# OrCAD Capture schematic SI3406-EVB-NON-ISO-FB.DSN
size B; title: Si3402 Eval Board - Isolated; rev: 2.2; note: SI3406-EVB-NON-ISO-FB
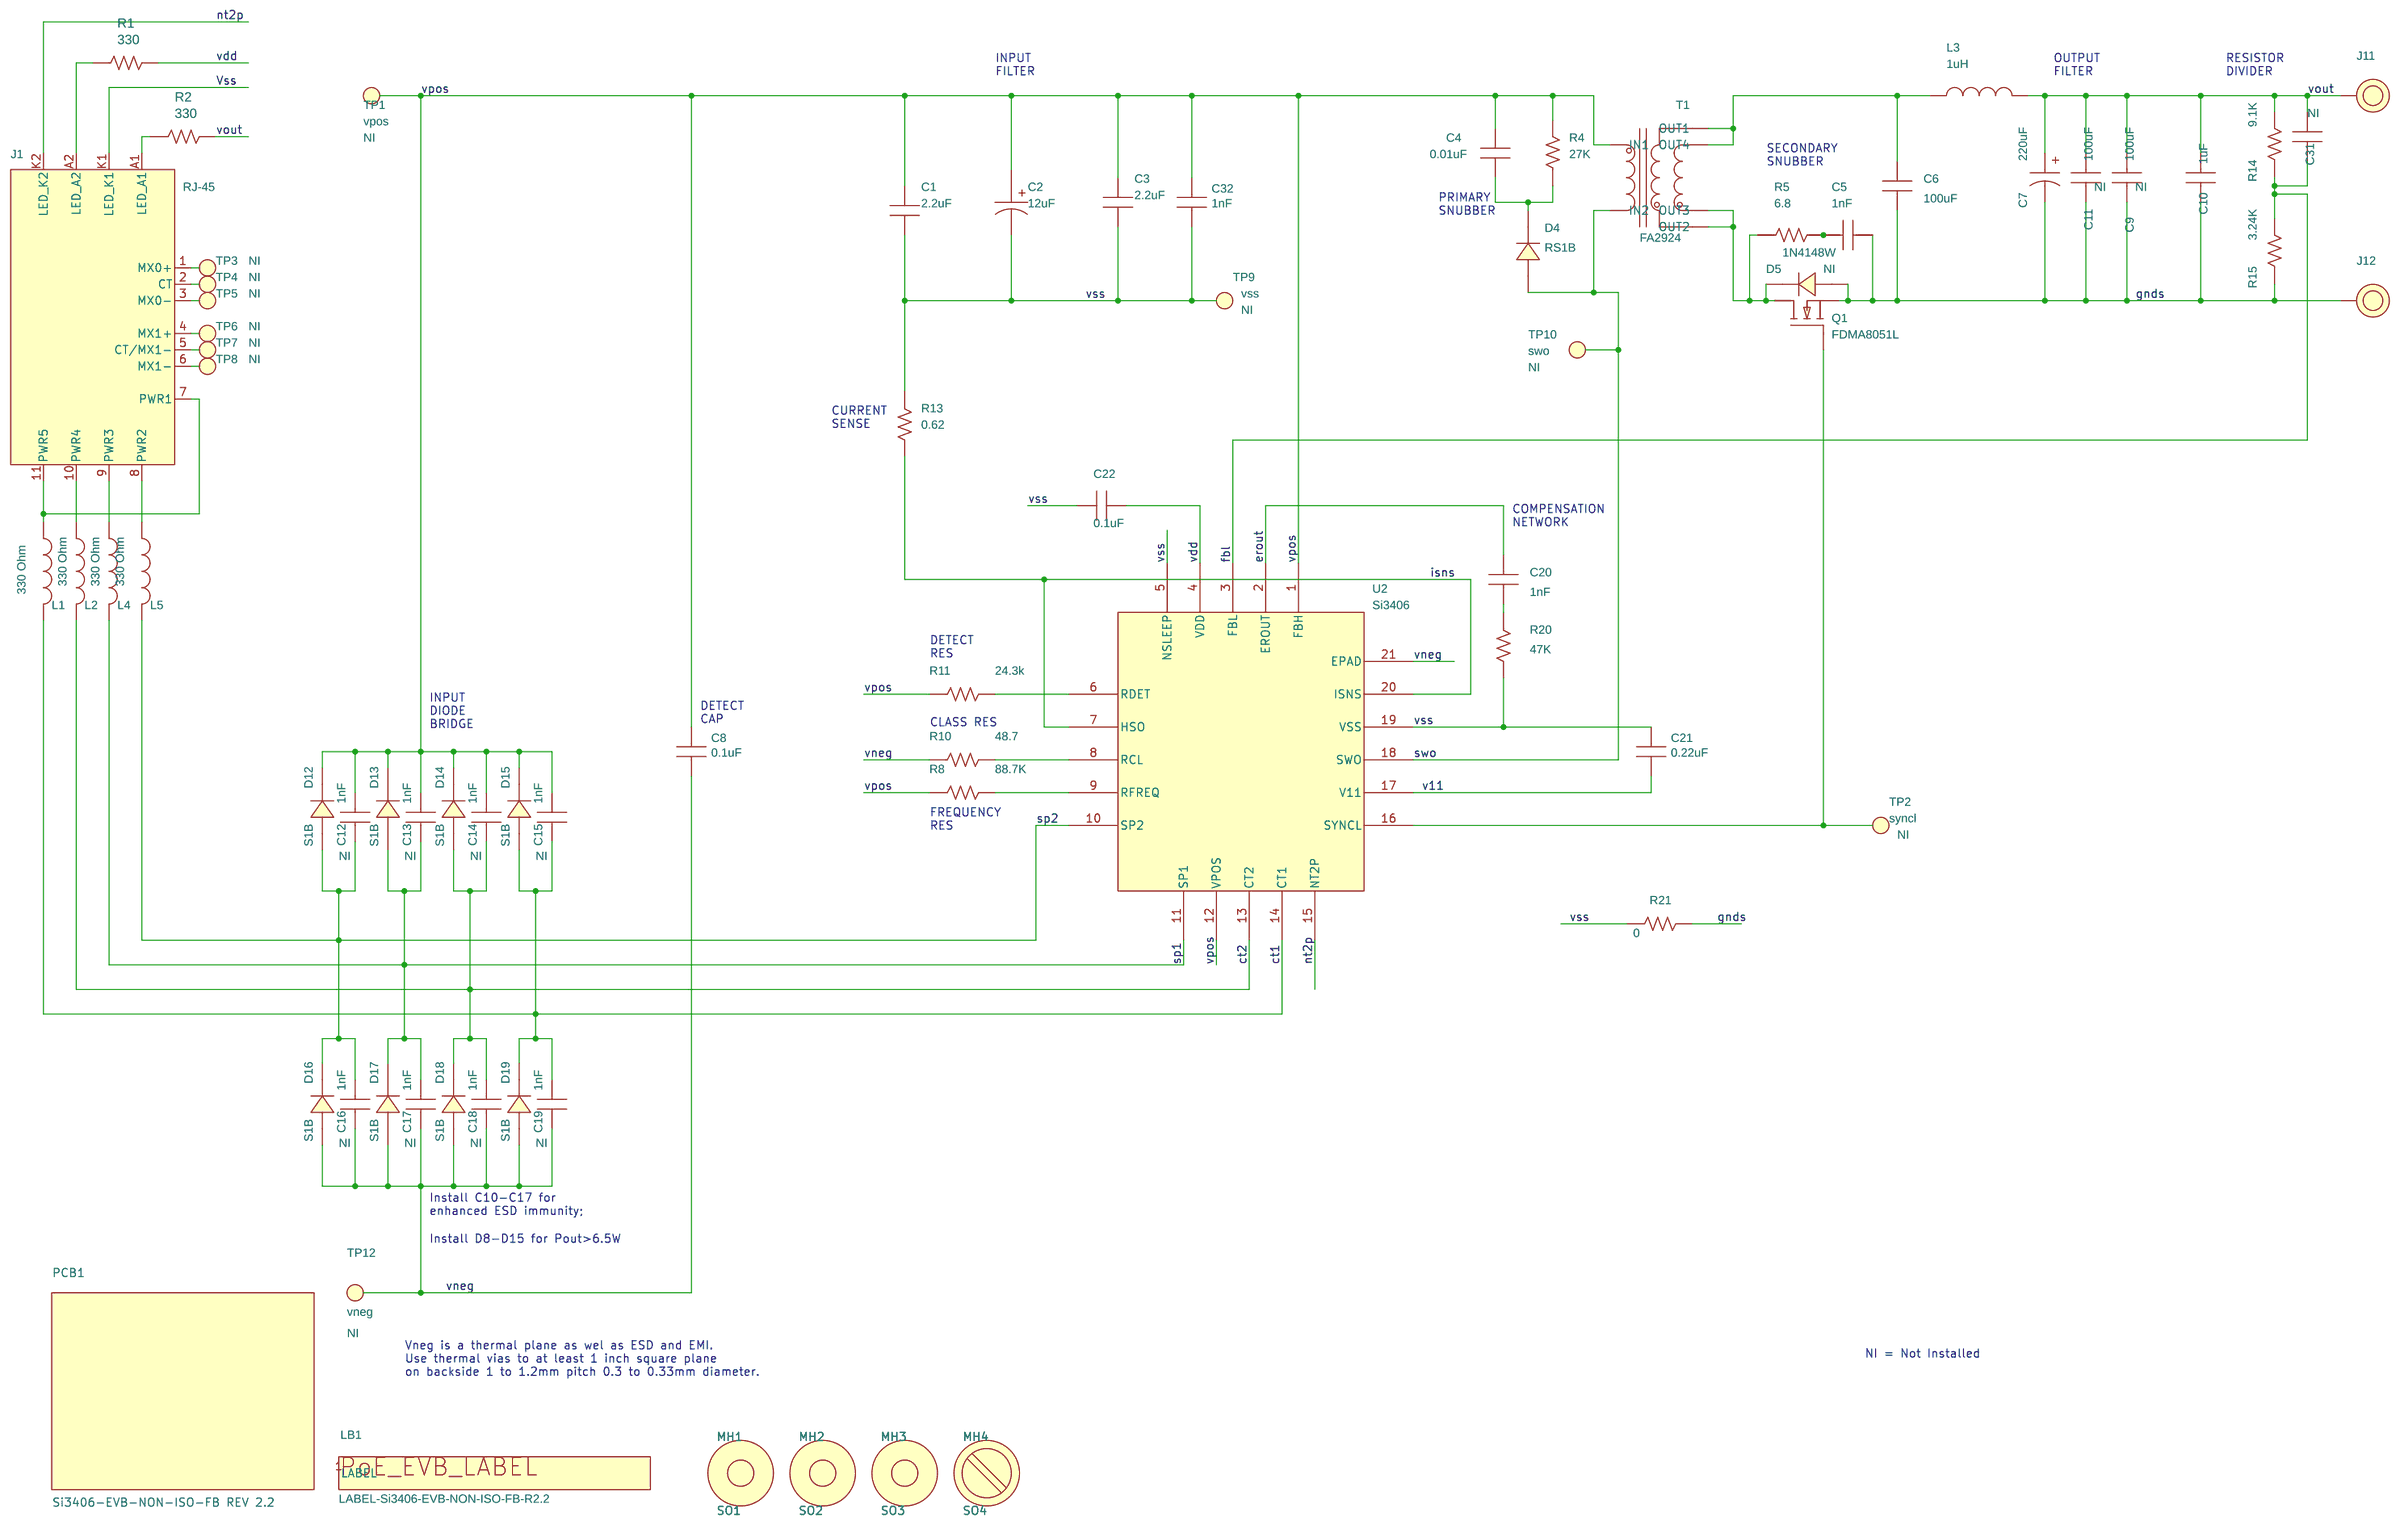
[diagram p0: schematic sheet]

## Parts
C1  2.2uF  [C1210]
C2  12uF  [C2.5X6.3MM-RAD]
C3  2.2uF  [C1210]
C4  0.01uF  [C0805]
C5  1nF  [C0805]
C6  100uF  [C1210]
C7  220uF  [C2X5MM-RAD]
C8  0.1uF  [C0805]
C9  100uF  [C1210]
C10  1uF  [C0603]
C11  100uF  [C1210]
C12  1nF  [C0603]
C13  1nF  [C0603]
C14  1nF  [C0603]
C15  1nF  [C0603]
C16  1nF  [C0603]
C17  1nF  [C0603]
C18  1nF  [C0603]
C19  1nF  [C0603]
C20  1nF  [C0805]
C21  0.22uF  [C0805]
C22  0.1uF  [C0805]
C31  330pF  [C0805]
C32  1nF  [C0603]
D4  RS1B  [DO-214AC]
D5  1N4148W  [SOD-123]
D12  S1B  [DO-214AC]
D13  S1B  [DO-214AC]
D14  S1B  [DO-214AC]
D15  S1B  [DO-214AC]
D16  S1B  [DO-214AC]
D17  S1B  [DO-214AC]
D18  S1B  [DO-214AC]
D19  S1B  [DO-214AC]
J1  RJ-45  [RJ45-SI-52004]
J11  BND_POST  [BANANA-JACK]
J12  BND_POST  [BANANA-JACK]
L1  330 Ohm  [L0805]
L2  330 Ohm  [L0805]
L3  1uH  [IND-6.6X4.45MM]
L4  330 Ohm  [L0805]
L5  330 Ohm  [L0805]
LB1  LABEL-Si3406-EVB-NON-ISO-FB-R2.2  [PTL-14-477]
MH1  4-40  [MH-125NP]
MH2  4-40  [MH-125NP]
MH3  4-40  [MH-125NP]
MH4  4-40  [MH-125NP]
PCB1  Si3406-EVB-NON-ISO-FB REV 2.2  [N/A]
Q1  FDMA8051L  [DFN6N2X2P0.65E1.0X1.05]
R1  330  [R0805]
R2  330  [R0805]
R4  27K  [R0805]
R5  6.8  [R0805]
R8  88.7K  [R0805]
R10  48.7  [R0805]
R11  24.3k  [R0805]
R13  0.62  [R0805]
R14  9.1K  [R0805]
R15  3.24K  [R0805]
R20  47K  [R0805]
R21  0  [R0805]
SO1  STANDOFF
SO2  STANDOFF
SO3  STANDOFF
SO4  STANDOFF
T1  FA2924  [XFMR-FA2924]
TP1  BLUE  [TESTPOINT]
TP2  BLUE  [TESTPOINT]
TP3  BLUE  [TESTPOINT]
TP4  BLUE  [TESTPOINT]
TP5  BLUE  [TESTPOINT]
TP6  BLUE  [TESTPOINT]
TP7  BLUE  [TESTPOINT]
TP8  BLUE  [TESTPOINT]
TP9  BLUE  [TESTPOINT]
TP10  BLUE  [TESTPOINT]
TP12  BLUE  [TESTPOINT]
U2  Si3406  [QFN20N5X5P0.8]

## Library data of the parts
C1 C3 = CAP_NP: CAP, 2.2uF, 100V, ±10%, X7R, 1210; Manufacturer: Samsung; ManufacturerPN: CL32B225KCJSNNE; SiLabsPN: CL32B225KCJSNNE; Tolerance: ±10%; Type: X7R; Voltage: 100V; Datasheet: MLCC.pdf
C2 = CAP_POL: CAP, 12uF, 100V, ±20%, AL, 6.3X11.2MM; Manufacturer: Panasonic; ManufacturerPN: EEUFC2A120; Part_Type: CAP/POL; SiLabsPN: EEUFC2A120; Tolerance: ±20%; Type: Alum_Elec; Voltage: 100V; Datasheet: ABA0000CE22.pdf
C4 = CAP_NP: CAP, 0.01uF, 100V, ±10%, X7R, 0805; Manufacturer: Venkel; ManufacturerPN: C0805X7R101-103K; SiLabsPN: C0805X7R101-103K; Tolerance: ±10%; Type: X7R; Voltage: 100V; Datasheet: PID_C.pdf
C5 C20 = CAP_NP: CAP, 1nF, 50V, ±1%, C0G, 0805; Manufacturer: Venkel; ManufacturerPN: C0805C0G500-102F; SiLabsPN: C0805C0G500-102F; Tolerance: ±1%; Type: C0G; Voltage: 50V; Datasheet: PID_C.pdf
C6 = CAP_NP: CAP, 100uF, 6.3V, ±10%, X5R, 1210; Manufacturer: Venkel; ManufacturerPN: C1210X5R6R3-107K; SiLabsPN: C1210X5R6R3-107K; Tolerance: ±10%; Type: X5R; Voltage: 6.3V; Datasheet: PID_C.pdf
C7 = CAP_POL_ALT: CAP, 220uF, 6.3V, ±20%, AL, RAD; FPLIST: C2X5MM-RAD,C2.0X5MM-RAD; Manufacturer: Panasonic; ManufacturerPN: ECA0JM221; SiLabsPN: ECA0JM221; Tolerance: ±20%; Type: Alum_Elec; Voltage: 6.3V; Datasheet: ABA0000CE12.pdf
C8 C22 = CAP_NP: CAP, 0.1uF, 100V, ±10%, X7R, 0805; Manufacturer: Venkel; ManufacturerPN: C0805X7R101-104K; SiLabsPN: C0805X7R101-104K; Tolerance: ±10%; Type: X7R; Voltage: 100V; Datasheet: PID_C.pdf
C9 C11 = CAP_NP: CAP, 100uF, 6.3V, ±10%, X5R, 1210; Installed Component: NI; Manufacturer: Venkel; ManufacturerPN: C1210X5R6R3-107K; SiLabsPN: C1210X5R6R3-107K; Tolerance: ±10%; Type: X5R; Voltage: 6.3V; Datasheet: PID_C.pdf
C10 = CAP_NP: CAP, 1uF, 6.3V, ±10%, X5R, 0603; Manufacturer: Venkel; ManufacturerPN: C0603X5R6R3-105K; SiLabsPN: C0603X5R6R3-105K; Tolerance: ±10%; Type: X5R; Voltage: 6.3V; Datasheet: PID_C.pdf
C12-C19 = CAP_NP: CAP, 1nF, 100V, ±10%, X7R, 0603; Installed Component: NI; Manufacturer: Venkel; ManufacturerPN: C0603X7R101-102K; SiLabsPN: C0603X7R101-102K; Tolerance: ±10%; Type: X7R; Voltage: 100V; Datasheet: PID_C.pdf
C21 = CAP_NP: CAP, 0.22uF, 10V, ±10%, X7R, 0805; Manufacturer: Venkel; ManufacturerPN: C0805X7R100-224K; SiLabsPN: C0805X7R100-224K; Tolerance: ±10%; Type: X7R; Voltage: 10V; Datasheet: PID_C.pdf
C31 = CAP_NP: CAP, 330pF, 100V, ±20%, X7R, 0805; Installed Component: NI; Manufacturer: Venkel; ManufacturerPN: C0805X7R101-331M; SiLabsPN: C0805X7R101-331M; Tolerance: ±20%; Type: X7R; Voltage: 100V; Datasheet: PID_C.pdf
C32 = CAP_NP: CAP, 1nF, 100V, ±10%, X7R, 0603; Manufacturer: Venkel; ManufacturerPN: C0603X7R101-102K; SiLabsPN: C0603X7R101-102K; Tolerance: ±10%; Type: X7R; Voltage: 100V; Datasheet: PID_C.pdf
D4 = DIODE: DIO, SINGLE, 100V, 1.0A, SMA; Manufacturer: Fairchild; Rating: 1.0A; Type: Single; Voltage: 100V; Datasheet: RS1A.pdf
D5 = DIODE: DIO, SINGLE, 100V, 300mA, SOD123; Installed Component: NI; Manufacturer: Diodes Inc.; ManufacturerPN: 1N4148W-7-F; Rating: 300mA; SiLabsPN: 1N4148W-7-F; Type: Single; Voltage: 100V; Datasheet: ds30086.pdf
D12-D19 = DIODE: DIO, SINGLE, 100V, 1.0A, SMA; Manufacturer: Fairchild; Rating: 1.0A; Type: Single; Voltage: 100V; Datasheet: S1A.pdf
J1 = MAGJACK_3: CONN, RJ-45, MAGJACK, 1 Port PoE; Manufacturer: Bel; ManufacturerPN: SI-52003-F; SiLabsPN: SI-52003-F; Type: Receptacle; Datasheet: SI-52003-F.pdf
J11 = BINDING-POST: CONN, BANANA JACK, Threaded uninsulated; Manufacturer: ABBATRON HH SMITH; ManufacturerPN: 101; Rating: 15A; SiLabsPN: 101; Silk: +; Type: BANANA; Datasheet: SD-101.pdf
J12 = BINDING-POST: CONN, BANANA JACK, Threaded uninsulated; Manufacturer: ABBATRON HH SMITH; ManufacturerPN: 101; Rating: 15A; SiLabsPN: 101; Type: BANANA; Datasheet: SD-101.pdf
L1 L2 L4 L5 = Ferrite_Bead: FERRITE BEAD, 330 Ohm @100MHZ, 0805; Manufacturer: MuRata; ManufacturerPN: BLM21PG331SN1; Part_Type: IND/FB; Rating: 1500mA; SiLabsPN: BLM21PG331SN1; Type: SMT; Datasheet: Murata BLM Ferrites.pdf
L3 = INDUCTOR: INDUCTOR, POWER, 1uH; Manufacturer: Coilcraft; ManufacturerPN: DO1608C-102ML_; Rating: 2.9A; SiLabsPN: DO1608C-102ML_; Tolerance: ±20%; Type: Shielded; Datasheet: do1608c.pdf
LB1 = PoE_EVB_Label: LABEL, PDB, POLYIMIDE, WHITE, 1.00 in. X 0.187 in., FONT 2; Manufacturer: Skyworks; Type: POLYIMIDE, WHITE; Datasheet: Brady TLS2200 Label PTL-14-477.pdf
MH1-MH4 = SCREW-Small: HDW, SCREW, 4-40 x 1/4 in. Pan Head, Slotted, Nylon; Manufacturer: Richco Plastic Co; ManufacturerPN: NSS-4-4-01; SiLabsPN: NSS-4-4-01; Type: SCREW; Datasheet: RichcoPlasticCo_Screws.pdf
PCB1 = PCB: PCB, BARE BOARD, Si3406-EVB-NON-ISO-FB-REV 2.2; Manufacturer: Skyworks; Type: BARE PCB
Q1 = NFET_DDGSDDD: TRANSISTOR, MOSFET, N-CHNL, 40V, 10A, 2.4W Switching Logic Level, SMT; Manufacturer: Fairchild; Rating: 10A; Type: N-CHNL; Voltage: 40V; Datasheet: FDMA8051L.pdf
R1 R2 = RES_V: RES, 330 Ohm, 1/10W, ±1%, ThickFilm, 0805; Manufacturer: Venkel; ManufacturerPN: CR0805-10W-3300F; Part_Type: RES/SMT; Rating: 1/10W; SiLabsPN: CR0805-10W-3300F; Tolerance: ±1%; Type: ThickFilm; Datasheet: PID_CR.pdf
R4 = RES: RES, 27K, 1/10W, ±1%, ThickFilm, 0805; Manufacturer: Venkel; ManufacturerPN: CR0805-10W-2702F; Rating: 1/10W; SiLabsPN: CR0805-10W-2702F; Tolerance: ±1%; Type: ThickFilm; Datasheet: PID_CR.pdf
R5 = RES: RES, 6.8 Ohm, 1/8W, ±1%, ThickFilm, 0805; Manufacturer: Yageo; ManufacturerPN: RC0805FR-076R8L; Rating: 1/8W; SiLabsPN: CR0805-8W-6R80F; Tolerance: ±1%; Type: ThickFilm; Datasheet: PID_CR.pdf
R8 = RES: RES, 88.7K, 1/8W, ±1%, ThickFilm, 0805; Manufacturer: Vishay; ManufacturerPN: CRCW080588K7FKEA; Rating: 1/8W; SiLabsPN: CR0805-8W-8872F; Tolerance: ±1%; Type: ThickFilm; Datasheet: dcrcwe3-109170.pdf
R10 = RES: RES, 48.7 Ohm, 1/8W, ±1%, ThickFilm, 0805; Manufacturer: vishay; ManufacturerPN: CRCW080548R7FKTA; Rating: 1/8W; SiLabsPN: CR0805-8W-48R7F; Tolerance: ±1%; Type: ThickFilm; Datasheet: dcrcwe3-109170.pdf
R11 = RES: RES, 24.3k, 1/8W, ±1%, ThickFilm, 0805; Manufacturer: vishay; ManufacturerPN: CRCW080524K3FKEA; Rating: 1/8W; SiLabsPN: CR0805-8W-2432F; Tolerance: ±1%; Type: ThickFilm; Datasheet: dcrcwe3-109170.pdf
R13 = RES: RES, 0.62 Ohm, 1/8W, ±1%, ThickFilm, 0805; Manufacturer: Yageo; ManufacturerPN: RL0805FR-070R62L; Rating: 1/8W; SiLabsPN: CR0805-8W-R620F; Tolerance: ±1%; Type: ThickFilm; Datasheet: PYu-RL_Group_521_RoHS_L 1.pdf
R14 = RES: RES, 9.1K, 1/8W, ±1%, ThickFilm, 0805; Manufacturer: Yageo; ManufacturerPN: RC0805FR-079K1L; Rating: 1/8W; SiLabsPN: CR0805-8W-9101F; Tolerance: ±1%; Type: ThickFilm; Datasheet: PYu-RC_Group_51_RoHS_L_8.pdf
R15 = RES: RES, 3.24K, 1/8W, ±1%, ThickFilm, 0805; Manufacturer: Vishay; ManufacturerPN: CRCW08053K24FKEA; Rating: 1/8W; SiLabsPN: CR0805-8W-3241F; Tolerance: ±1%; Type: ThickFilm; Datasheet: dcrcwe3-109170.pdf
R20 = RES: RES, 47K, 1/10W, ±5%, ThickFilm, 0805; Manufacturer: Venkel; ManufacturerPN: CR0805-10W-473J; Rating: 1/10W; SiLabsPN: CR0805-10W-473J; Tolerance: ±5%; Type: ThickFilm; Datasheet: PID_CR.pdf
R21 = RES: RES, 0 Ohm, 2A, ThickFilm, 0805; Manufacturer: Venkel; ManufacturerPN: CR0805-10W-000; Rating: 2A; SiLabsPN: CR0805-10W-000; Type: ThickFilm; Datasheet: PID_CR.pdf
SO1-SO4 = STANDOFF: HDW, STANDOFF, 4-40 X 1/2" , Nylon; Manufacturer: SPC Technology; ManufacturerPN: 2397; SiLabsPN: 2397; Datasheet: SPC_Technology_spacers.pdf
T1 = XFMR_FA2805: TRANSFORMER, Flyback, 3.3V; Manufacturer: Coilcraft; ManufacturerPN: FA2924-AL; SiLabsPN: FA2924-AL; Datasheet: fa2805.pdf
TP1 = TEST_POINT: TESTPOINT, BLUE, PTH; Installed Component: NI; Manufacturer: Kobiconn; ManufacturerPN: 151-205-RC; SiLabsPN: 151-205; Silk: vpos; Type: Loop; Datasheet: KC-300780.pdf
TP2 = TEST_POINT: TESTPOINT, BLUE, PTH; Installed Component: NI; Manufacturer: Kobiconn; ManufacturerPN: 151-205-RC; SiLabsPN: 151-205; Silk: syncl; Type: Loop; Datasheet: KC-300780.pdf
TP3-TP8 = TEST_POINT: TESTPOINT, BLUE, PTH; Installed Component: NI; Manufacturer: Kobiconn; ManufacturerPN: 151-205-RC; SiLabsPN: 151-205; Type: Loop; Datasheet: KC-300780.pdf
TP9 = TEST_POINT: TESTPOINT, BLUE, PTH; Installed Component: NI; Manufacturer: Kobiconn; ManufacturerPN: 151-205-RC; SiLabsPN: 151-205; Silk: vss; Type: Loop; Datasheet: KC-300780.pdf
TP10 = TEST_POINT: TESTPOINT, BLUE, PTH; Installed Component: NI; Manufacturer: Kobiconn; ManufacturerPN: 151-205-RC; SiLabsPN: 151-205; Silk: swo; Type: Loop; Datasheet: KC-300780.pdf
TP12 = TEST_POINT: TESTPOINT, BLUE, PTH; Installed Component: NI; Manufacturer: Kobiconn; ManufacturerPN: 151-205-RC; SiLabsPN: 151-205; Silk: vneg; Type: Loop; Datasheet: KC-300780.pdf
U2 = Si3406: IC, FULLY-INTEGRATED 802.3-COMPLIANT PoE PD INTERFACE AND LOW-EMI SWITCHING REGULATOR, QFN20; Manufacturer: Skyworks; ManufacturerPN: Si3406-A-GM; SiLabsPN: Si3406-A-GM; Type: PD; Voltage: 120V; Datasheet: si3406x-datasheet.pdf

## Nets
gnds: C5.2 C6.1 C7.2 C9.2 C10.2 C11.2 D5.A(ANODE) J12.1(BP) Q1.S(SOURCE) R15.1 R21.2
v11: C21.2 U2.17(V11)
vdd: C22.2 R1.1 U2.4(VDD)
Vss: C1.1 C2.2 C3.1 C21.1 C22.1 C32.2 J1.K1(LED) R13.1 R20.2 R21.1 TP9.1(Point) U2.5(NSLEEP) U2.19(VSS)
ct1: C15.1 C19.2 D15.A(ANODE) D19.K(CATHODE) L1.2 U2.14(CT1)
ct2: C14.1 C18.2 D14.A(ANODE) D18.K(CATHODE) L2.2 U2.13(CT2)
erout: C20.2 U2.2(EROUT)
fbl: C31.2 R14.1 R15.2 U2.3(FBL)
isns: R13.2 U2.7(HSO) U2.20(ISNS)
LABEL: LB1.1(LABEL)
nt2p: J1.K2(LED) U2.15(NT2P)
sp1: C13.1 C17.2 D13.A(ANODE) D17.K(CATHODE) L4.2 U2.11(SP1)
sp2: C12.1 C16.2 D12.A(ANODE) D16.K(CATHODE) L5.2 U2.10(SP2)
swo: D4.A(ANODE) T1.1(IN2) TP10.1(Point) U2.18(SWO)
vneg: C8.2 C16.1 C17.1 C18.1 C19.1 D16.A(ANODE) D17.A(ANODE) D18.A(ANODE) D19.A(ANODE) R10.1 TP12.1(Point) U2.21(EPAD)
vout: C7.1 C9.1 C10.1 C11.1 C31.1 J11.1(BP) L3.2 R2.1 R14.2
vpos: C1.2 C2.1 C3.2 C4.1 C8.1 C12.2 C13.2 C14.2 C15.2 C32.1 D12.K(CATHODE) D13.K(CATHODE) D14.K(CATHODE) D15.K(CATHODE) R4.2 R8.1 R11.1 T1.2(IN1) TP1.1(Point) U2.1(FBH) U2.12(VPOS)
N317144: J1.A1(LED) R2.2
N1344300: J1.A2(LED) R1.2
N1417624: J1.7(PWR1) J1.11(PWR5) L1.1
N1446659: C4.2 D4.K(CATHODE) R4.1
N1453435: D5.K(CATHODE) Q1.D1(DRAIN) Q1.D2(DRAIN) Q1.D3(DRAIN) Q1.D4(DRAIN) Q1.D5(DRAIN) R5.1 T1.7(OUT2) T1.8(OUT3)
N1457427: R10.2 U2.8(RCL)
N1476158: Q1.G(GATE) TP2.1(Point) U2.16(SYNCL)
N1482498: R11.2 U2.6(RDET)
N1484477: R8.2 U2.9(RFREQ)
N1498307: C6.2 L3.1 T1.9(OUT1) T1.10(OUT4)
N1505711: J1.1(MX0+) TP3.1(Point)
N1505935: J1.6(MX1-) TP8.1(Point)
N1505939: J1.5(CT/MX1-) TP7.1(Point)
N1505943: J1.4(MX1+) TP6.1(Point)
N1505947: J1.3(MX0-) TP5.1(Point)
N1505951: J1.2(CT) TP4.1(Point)
N1524736: C5.1 R5.2
N1527876: J1.8(PWR2) L5.1
N1527880: J1.9(PWR3) L4.1
N1527949: J1.10(PWR4) L2.1
N1548116: C20.1 R20.1

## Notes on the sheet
- INPUT
  FILTER
- OUTPUT
  FILTER
- RESISTOR
  DIVIDER
- SECONDARY
  SNUBBER
- PRIMARY
  SNUBBER
- CURRENT
  SENSE
- COMPENSATION
  NETWORK
- DETECT
  RES
- INPUT
  DIODE
  BRIDGE
- DETECT
  CAP
- CLASS RES
- FREQUENCY
  RES
- Install C10-C17 for
  enhanced ESD immunity;
- Install D8-D15 for Pout>6.5W
- Vneg is a thermal plane as wel as ESD and EMI.
  Use thermal vias to at least 1 inch square plane
  on backside 1 to 1.2mm pitch 0.3 to 0.33mm diameter.
- NI = Not Installed
